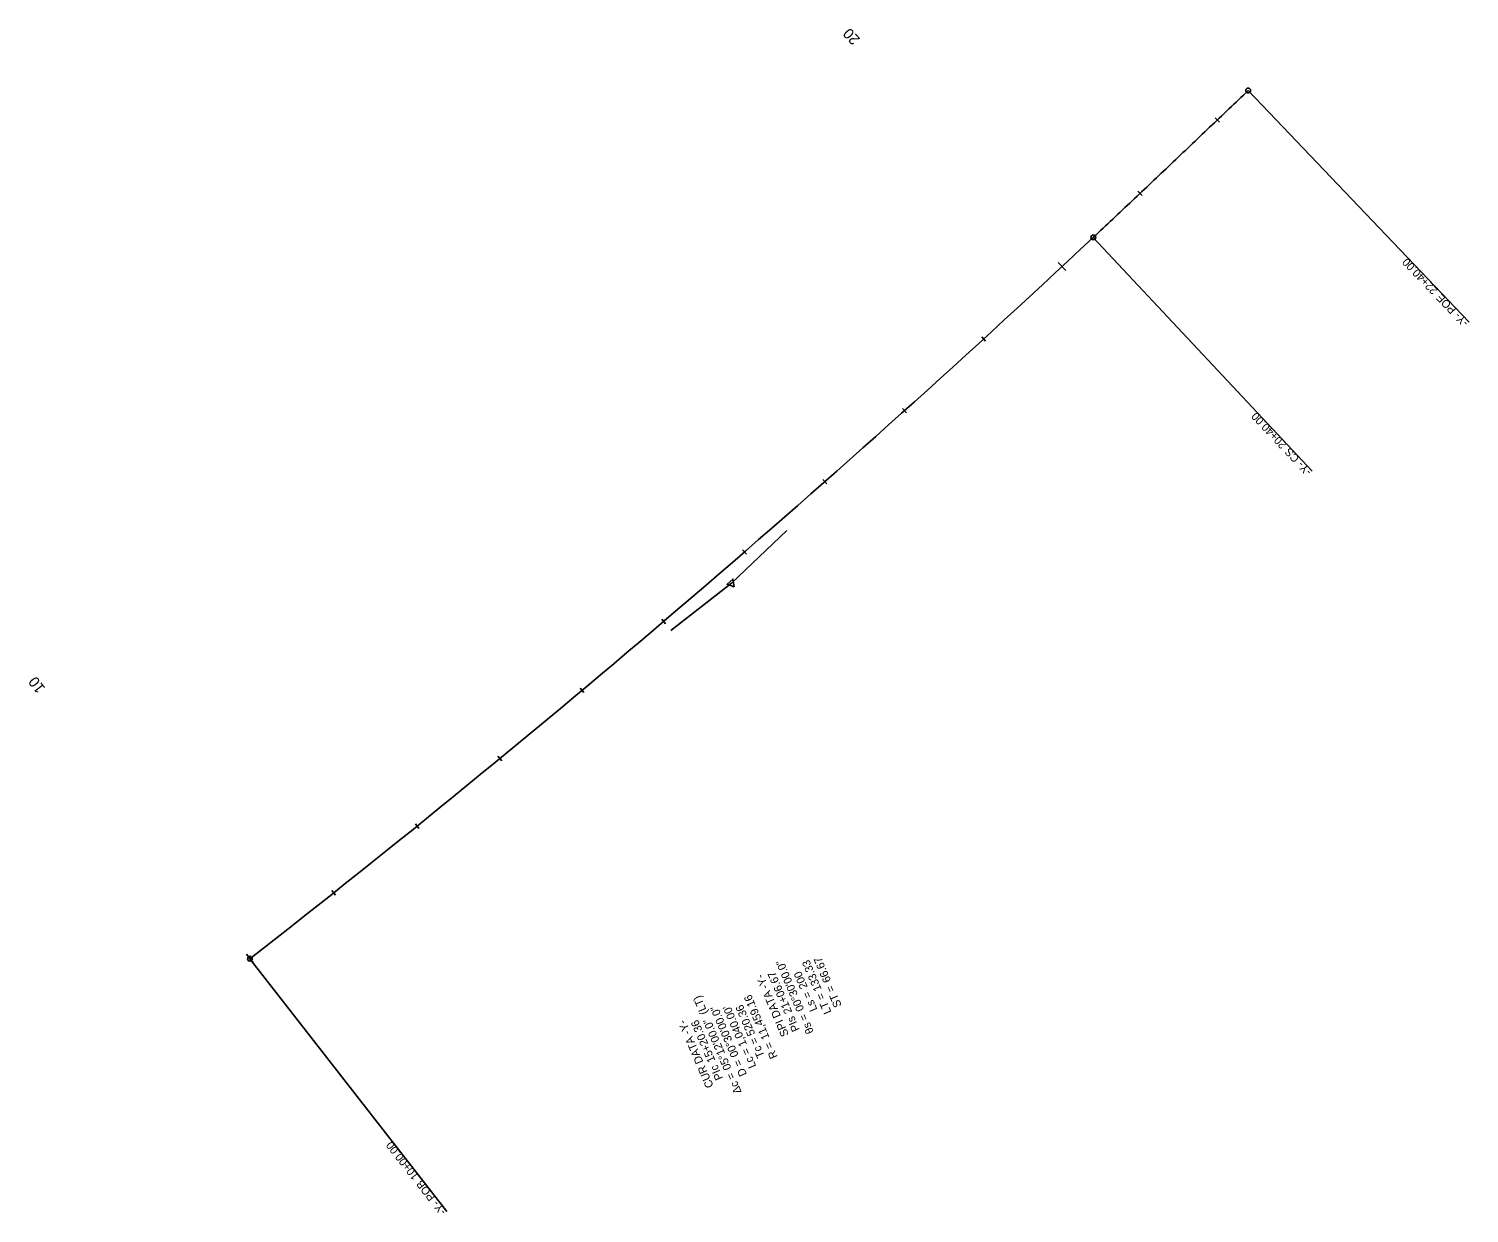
# Model space of a CAD drawing. Extents: x 1551083 to 1552433, y 810048 to 811158.
import ezdxf

# ---------------------------------------------------------------- set-up
doc = ezdxf.new("R2010")
doc.units = 0
for name, color, linetype in [('_CIVIL_CONSTRUCTION', 7, 'Continuous'), ('Default', 7, 'Continuous'), ('P_HYD_Contour_Minor', 7, 'Continuous'), ('P_HYD_TL_Ditch_Base', 7, 'Continuous'), ('P_HYD_TL_Ditch_Boundary', 7, 'Continuous'), ('P_HYD_TL_Ditch_Mid', 7, 'Continuous'), ('P_HYD_TL_Slope_Stake_Fill', 7, 'Continuous')]:
    doc.layers.add(name, color=color, linetype=linetype)

msp = doc.modelspace()

# ---------------------------------------------------------------- linework, layer by layer
at = {"layer": '_CIVIL_CONSTRUCTION'}
msp.add_arc((1544245.7, 819324.7), 11459.2, 307.93361, 313.13361, dxfattribs=at)
msp.add_open_spline([(1552080.4, 810962.2), (1552092.5, 810973.6), (1552116.8, 810996.5), (1552153.1, 811030.8), (1552189.3, 811065.3), (1552213.5, 811088.3), (1552225.5, 811099.8)], degree=3, dxfattribs=at)
at = {"layer": 'Default'}
for q in [(1551793.4, 810687.8), (1551684.5, 810593.9), (1551741.3, 810638.2)]:
    msp.add_line((1551741.3, 810638.2), q, dxfattribs=at)
msp.add_lwpolyline([(1551744, 810635), (1551742.7, 810642.1), (1551737.2, 810637.4)], close=True, dxfattribs=at)
at = {"layer": 'P_HYD_TL_Ditch_Base'}
for p, q in [((1552194.7, 811074.2), (1552198.5, 811070.2)), ((1552122.2, 811005.4), (1552126, 811001.3)), ((1551975.8, 810869.2), (1551979.5, 810865.1)), ((1551901.7, 810802), (1551905.4, 810797.9)), ((1551827, 810735.5), (1551830.7, 810731.4)), ((1551751.8, 810669.7), (1551755.4, 810665.5)), ((1551676, 810604.5), (1551679.5, 810600.3)), ((1551599.6, 810540), (1551603.1, 810535.8)), ((1551522.6, 810476.2), (1551526.2, 810471.9)), ((1551445.2, 810413), (1551448.6, 810408.7)), ((1551367.1, 810350.5), (1551370.5, 810346.2))]:
    msp.add_line(p, q, dxfattribs=at)
at = {"layer": 'P_HYD_TL_Ditch_Mid'}
for p, q in [((1552047.5, 810938.8), (1552054.7, 810931.1)), ((1551286.9, 810290.8), (1551293.5, 810282.4))]:
    msp.add_line(p, q, dxfattribs=at)
at = {"layer": 'P_HYD_TL_Slope_Stake_Fill'}
for p, q in [((1552225.5, 811099.8), (1552432.5, 810882.7)), ((1552080.4, 810962.2), (1552285.5, 810743.3)), ((1551290.2, 810286.6), (1551474.6, 810049.9))]:
    msp.add_line(p, q, dxfattribs=at)
for centre in [(1552225.5, 811099.8), (1552080.4, 810962.2), (1551290.2, 810286.6)]:
    msp.add_circle(centre, 2.25, dxfattribs=at)

# ---------------------------------------------------------------- texts
at = {"layer": 'P_HYD_Contour_Minor'}
for s, p in [('00°30\'00.0"', (1551809.7, 810239.1)), ('133.33', (1551826.1, 810258)), ('66.67', (1551834.9, 810266)), ('Y', (1551774.9, 810263.3)), ('-', (1551772.1, 810269.8)), ('SPI DATA -', (1551795.3, 810215.5)), ('21+06.67', (1551798.4, 810236.8)), ('200', (1551812.9, 810260.2)), (' (LT)', (1551720.4, 810233.4)), ('11,459.16', (1551777.2, 810212.7)), ('Ls = ', (1551822, 810239)), ('LT = ', (1551835.2, 810236.6)), ('ST = ', (1551844.8, 810242.8)), ('00°30\'00.0"', (1551748.3, 810196.2)), ("Lc = 1,040.00'", (1551764.7, 810185.9)), ('520.36', (1551763.8, 810216.1)), ('Y', (1551702, 810220.6)), ('-', (1551699.3, 810227)), ('15+20.36', (1551726.5, 810191.3)), ('05°12\'00.0"', (1551741.5, 810184.1)), ('PIs ', (1551805.5, 810220.2)), ('θs = ', (1551818.7, 810218)), ('CUR DATA -', (1551724.8, 810167.4)), ('Tc = ', (1551772.6, 810195.5)), ('R = ', (1551784.8, 810194.8)), ('PIc ', (1551733.6, 810174.7)), ('D = ', (1551756, 810178.3)), ('Δc = ', (1551751, 810161.9))]:
    msp.add_text(s, height=7.5, rotation=113.1736, dxfattribs=at).set_placement(p)
at = {"layer": 'P_HYD_TL_Ditch_Boundary'}
for s, rotation, p in [('20', 132.9336, (1551862.4, 811148.2)), ('10', 127.9336, (1551098.9, 810540.1))]:
    msp.add_text(s, height=10, rotation=rotation, dxfattribs=at).set_placement(p)
at = {"layer": 'P_HYD_TL_Slope_Stake_Fill'}
for s, rotation, p in [('22+40.00', 133.6336, (1552403.6, 810913)), ('POE', 133.6336, (1552420.9, 810894.9)), ('Y', 133.6336, (1552430.1, 810885.2)), ('- ', 133.6336, (1552425.3, 810890.3)), ('-', 133.6336, (1552432.5, 810882.7)), ('20+40.00', 133.1336, (1552262, 810768.4)), ('CS', 133.1336, (1552274, 810755.6)), ('Y', 133.1336, (1552283.1, 810745.8)), ('- ', 133.1336, (1552278.3, 810750.9)), ('-', 133.1336, (1552285.5, 810743.3)), ('10+00.00', 127.9336, (1551448.9, 810083)), ('POB', 127.9336, (1551464.3, 810063.3)), ('Y', 127.9336, (1551472.5, 810052.7)), ('- ', 127.9336, (1551468.2, 810058.2)), ('-', 127.9336, (1551474.6, 810049.9))]:
    msp.add_text(s, height=7.5, rotation=rotation, dxfattribs=at).set_placement(p)

doc.saveas('drawing.dxf')
